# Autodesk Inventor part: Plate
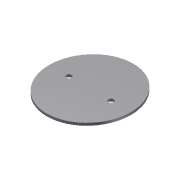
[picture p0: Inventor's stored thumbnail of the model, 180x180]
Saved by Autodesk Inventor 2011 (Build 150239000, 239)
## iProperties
Created: 2009-04
Part Number: Plate
Document SubType Name: Modeling
Designer: Sham
Density: 1 g/cm^3
Author: Sham
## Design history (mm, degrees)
sketch "Sketch1"
  geometry: C1 r 6.25 at (-50, 0); C2 r 6.25 at (50, 0); 4 further points; 1 other entity
  constraints: 2 centre point, 1 coincident, 5 other
  dimensions: "d1" = 12.5 diameter of C1; "d2" = 12.5 diameter of C2; "d3" = 100 distance of C2.centre C1.centre; "d4" = 102.5 distance of point (0, 0) point (0, 102.5); "d5" = 96.9 distance of point (0, 0) point (-96.9, 0); "d6" = 50 distance of point (0, 0) C1.centre
extrude "Extrusion1" new body sketch "Sketch1" distance "d7" = 6; taper "d8" = 0 deg
body "Solid1"
